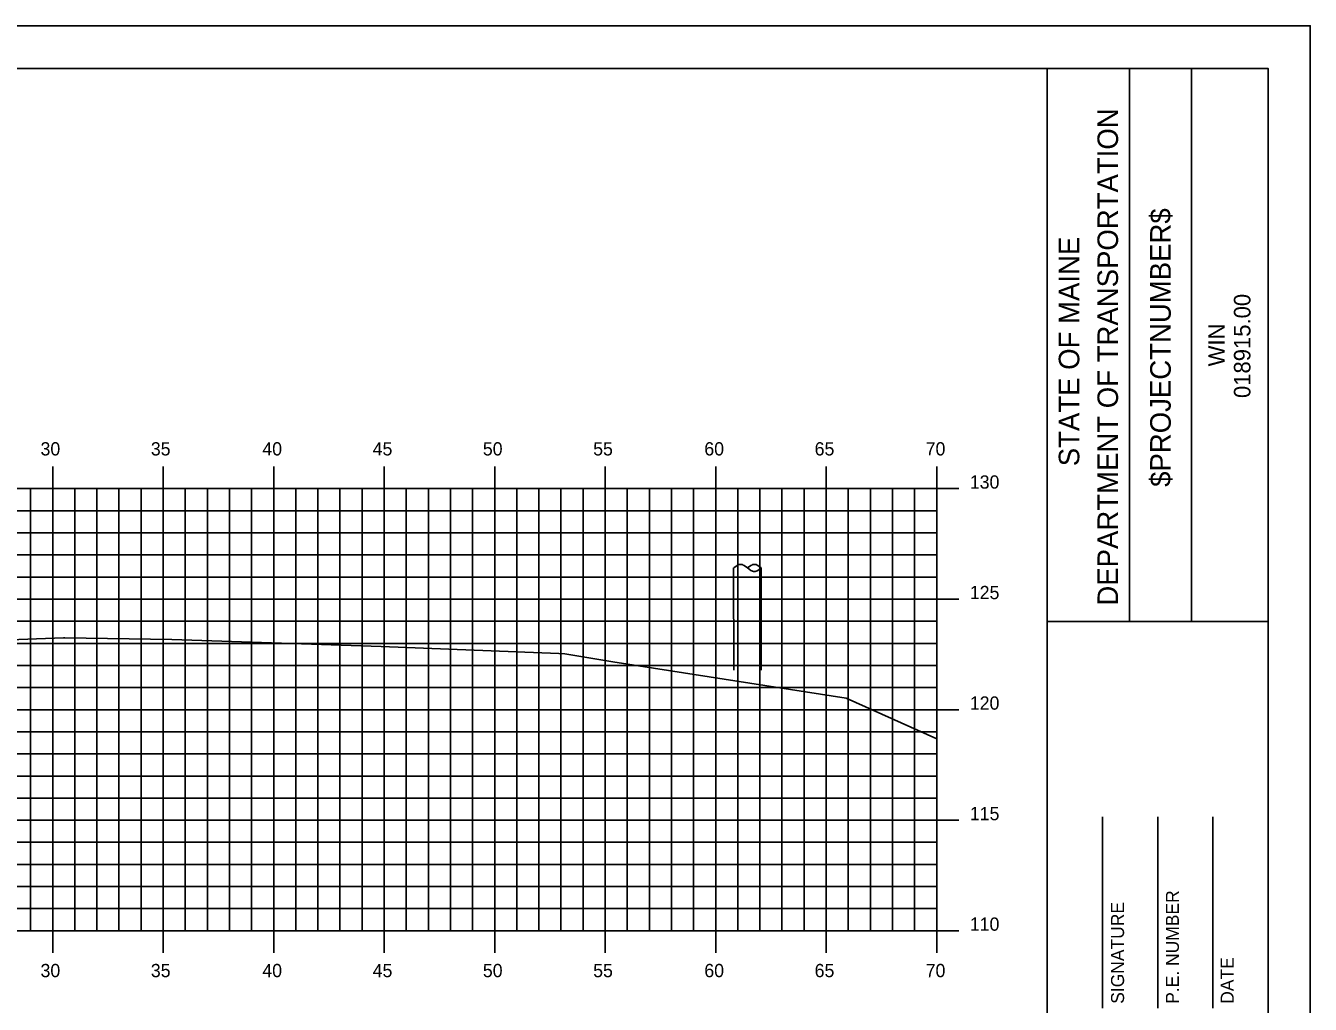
# Model space of a CAD drawing. Extents: x 852404 to 852575, y 365624 to 365734.
# Drawn here: x 852515.6 to 852573.7, y 365689.7 to 365734 of the extents above; entities that cross this region are included whole.
import ezdxf

# ---------------------------------------------------------------- set-up
doc = ezdxf.new("R2010")
doc.units = 0
for name, color, linetype in [('BORDER', 7, 'Continuous'), ('H_V ANNOTATION', 7, 'Continuous'), ('M_Roadway_Centerline', 7, 'Continuous'), ('MAJOR', 7, 'Continuous'), ('MINOR', 7, 'Continuous'), ('PLOT BOUNDARY', 7, 'Continuous'), ('S_Roadway_Centerline', 7, 'Continuous'), ('S_Utilities_Pole_StreetLight', 7, 'Continuous')]:
    doc.layers.add(name, color=color, linetype=linetype)

msp = doc.modelspace()

# ---------------------------------------------------------------- linework, layer by layer
at = {"layer": 'BORDER'}
for p, q in [((852561.792, 365627.027), (852561.792, 365732.027)), ((852565.521, 365707.024), (852565.521, 365732.024)), ((852568.316, 365707.024), (852568.316, 365732.024)), ((852561.793, 365707.021), (852571.792, 365707.021)), ((852564.292, 365689.53), (852564.292, 365698.177)), ((852566.792, 365689.53), (852566.792, 365698.177)), ((852569.292, 365689.53), (852569.292, 365698.177))]:
    msp.add_line(p, q, dxfattribs=at)
msp.add_lwpolyline([(852411.792, 365627.027), (852571.792, 365627.027), (852571.792, 365732.027), (852411.792, 365732.027)], close=True, dxfattribs=at)
at = {"layer": 'MAJOR'}
for p, q in [((852516.792, 365714.029), (852516.792, 365713.027)), ((852521.792, 365714.029), (852521.792, 365713.027)), ((852526.792, 365714.029), (852526.792, 365713.027)), ((852531.792, 365714.029), (852531.792, 365713.027)), ((852536.792, 365714.029), (852536.792, 365713.027)), ((852541.792, 365714.029), (852541.792, 365713.027)), ((852546.792, 365714.029), (852546.792, 365713.027)), ((852551.792, 365714.029), (852551.792, 365713.027)), ((852556.792, 365714.029), (852556.792, 365713.027)), ((852416.792, 365713.027), (852556.792, 365713.027)), ((852416.792, 365713.027), (852556.792, 365713.027)), ((852516.792, 365693.027), (852516.792, 365713.027)), ((852521.792, 365693.027), (852521.792, 365713.027)), ((852526.792, 365693.027), (852526.792, 365713.027)), ((852531.792, 365693.027), (852531.792, 365713.027)), ((852536.792, 365693.027), (852536.792, 365713.027)), ((852541.792, 365693.027), (852541.792, 365713.027)), ((852546.792, 365693.027), (852546.792, 365713.027)), ((852551.792, 365693.027), (852551.792, 365713.027)), ((852557.794, 365713.027), (852555.79, 365713.027)), ((852556.792, 365693.027), (852556.792, 365713.027)), ((852556.792, 365693.027), (852556.792, 365713.027)), ((852416.792, 365708.027), (852556.792, 365708.027)), ((852557.794, 365708.027), (852555.79, 365708.027)), ((852416.792, 365703.027), (852556.792, 365703.027)), ((852557.794, 365703.027), (852555.79, 365703.027)), ((852416.792, 365698.027), (852556.792, 365698.027)), ((852557.794, 365698.027), (852555.79, 365698.027)), ((852416.792, 365693.027), (852556.792, 365693.027)), ((852416.792, 365693.027), (852556.792, 365693.027)), ((852516.792, 365692.025), (852516.792, 365693.027)), ((852521.792, 365692.025), (852521.792, 365693.027)), ((852526.792, 365692.025), (852526.792, 365693.027)), ((852531.792, 365692.025), (852531.792, 365693.027)), ((852536.792, 365692.025), (852536.792, 365693.027)), ((852541.792, 365692.025), (852541.792, 365693.027)), ((852546.792, 365692.025), (852546.792, 365693.027)), ((852551.792, 365692.025), (852551.792, 365693.027)), ((852557.794, 365693.027), (852555.79, 365693.027)), ((852556.792, 365692.025), (852556.792, 365693.027))]:
    msp.add_line(p, q, dxfattribs=at)
at = {"layer": 'MINOR'}
for p, q in [((852515.792, 365693.027), (852515.792, 365713.027)), ((852517.792, 365693.027), (852517.792, 365713.027)), ((852518.792, 365693.027), (852518.792, 365713.027)), ((852519.792, 365693.027), (852519.792, 365713.027)), ((852520.792, 365693.027), (852520.792, 365713.027)), ((852522.792, 365693.027), (852522.792, 365713.027)), ((852523.792, 365693.027), (852523.792, 365713.027)), ((852524.792, 365693.027), (852524.792, 365713.027)), ((852525.792, 365693.027), (852525.792, 365713.027)), ((852527.792, 365693.027), (852527.792, 365713.027)), ((852528.792, 365693.027), (852528.792, 365713.027)), ((852529.792, 365693.027), (852529.792, 365713.027)), ((852530.792, 365693.027), (852530.792, 365713.027)), ((852532.792, 365693.027), (852532.792, 365713.027)), ((852533.792, 365693.027), (852533.792, 365713.027)), ((852534.792, 365693.027), (852534.792, 365713.027)), ((852535.792, 365693.027), (852535.792, 365713.027)), ((852537.792, 365693.027), (852537.792, 365713.027)), ((852538.792, 365693.027), (852538.792, 365713.027)), ((852539.792, 365693.027), (852539.792, 365713.027)), ((852540.792, 365693.027), (852540.792, 365713.027)), ((852542.792, 365693.027), (852542.792, 365713.027)), ((852543.792, 365693.027), (852543.792, 365713.027)), ((852544.792, 365693.027), (852544.792, 365713.027)), ((852545.792, 365693.027), (852545.792, 365713.027)), ((852547.792, 365693.027), (852547.792, 365713.027)), ((852548.792, 365693.027), (852548.792, 365713.027)), ((852549.792, 365693.027), (852549.792, 365713.027)), ((852550.792, 365693.027), (852550.792, 365713.027)), ((852552.792, 365693.027), (852552.792, 365713.027)), ((852553.792, 365693.027), (852553.792, 365713.027)), ((852554.792, 365693.027), (852554.792, 365713.027)), ((852555.792, 365693.027), (852555.792, 365713.027)), ((852416.792, 365712.027), (852556.792, 365712.027)), ((852556.792, 365712.027), (852555.79, 365712.027)), ((852416.792, 365711.027), (852556.792, 365711.027)), ((852556.792, 365711.027), (852555.79, 365711.027)), ((852416.792, 365710.027), (852556.792, 365710.027)), ((852556.792, 365710.027), (852555.79, 365710.027)), ((852416.792, 365709.027), (852556.792, 365709.027)), ((852556.792, 365709.027), (852555.79, 365709.027)), ((852416.792, 365707.027), (852556.792, 365707.027)), ((852556.792, 365707.027), (852555.79, 365707.027)), ((852416.792, 365706.027), (852556.792, 365706.027)), ((852556.792, 365706.027), (852555.79, 365706.027)), ((852416.792, 365705.027), (852556.792, 365705.027)), ((852556.792, 365705.027), (852555.79, 365705.027)), ((852416.792, 365704.027), (852556.792, 365704.027)), ((852556.792, 365704.027), (852555.79, 365704.027)), ((852416.792, 365702.027), (852556.792, 365702.027)), ((852556.792, 365702.027), (852555.79, 365702.027)), ((852416.792, 365701.027), (852556.792, 365701.027)), ((852556.792, 365701.027), (852555.79, 365701.027)), ((852416.792, 365700.027), (852556.792, 365700.027)), ((852556.792, 365700.027), (852555.79, 365700.027)), ((852416.792, 365699.027), (852556.792, 365699.027)), ((852556.792, 365699.027), (852555.79, 365699.027)), ((852416.792, 365697.027), (852556.792, 365697.027)), ((852556.792, 365697.027), (852555.79, 365697.027)), ((852416.792, 365696.027), (852556.792, 365696.027)), ((852556.792, 365696.027), (852555.79, 365696.027)), ((852416.792, 365695.027), (852556.792, 365695.027)), ((852556.792, 365695.027), (852555.79, 365695.027)), ((852416.792, 365694.027), (852556.792, 365694.027)), ((852556.792, 365694.027), (852555.79, 365694.027))]:
    msp.add_line(p, q, dxfattribs=at)
at = {"layer": 'PLOT BOUNDARY'}
msp.add_lwpolyline([(852403.699, 365623.968), (852573.699, 365623.968), (852573.699, 365733.968), (852403.699, 365733.968)], close=True, dxfattribs=at)
at = {"layer": 'S_Roadway_Centerline'}
msp.add_lwpolyline([(852514.448, 365706.178), (852517.274, 365706.274), (852517.34, 365706.273), (852522.187, 365706.197), (852531.654, 365705.889), (852539.699, 365705.561), (852539.969, 365705.546), (852542.133, 365705.196), (852552.698, 365703.551), (852556.792, 365701.707)], dxfattribs=at)
at = {"layer": 'S_Utilities_Pole_StreetLight'}
for p, q in [((852547.606, 365704.82), (852547.602, 365709.44)), ((852547.606, 365709.44), (852547.762, 365709.55)), ((852548.074, 365709.55), (852548.23, 365709.44)), ((852548.387, 365709.55), (852548.23, 365709.44)), ((852548.23, 365709.44), (852548.387, 365709.329)), ((852548.856, 365709.44), (852548.7, 365709.55)), ((852548.7, 365709.329), (852548.856, 365709.44)), ((852548.856, 365704.82), (852548.852, 365709.44))]:
    msp.add_line(p, q, dxfattribs=at)
for centre, start, end in [((852547.918, 365709.329), 90, 125.26439), ((852547.918, 365709.329), 54.73561, 90), ((852548.543, 365709.329), 90, 125.26439), ((852548.543, 365709.329), 54.73561, 90), ((852548.543, 365709.55), 234.73561, 270), ((852548.543, 365709.55), 270, 305.26439)]:
    msp.add_arc(centre, 0.271, start, end, dxfattribs=at)

# ---------------------------------------------------------------- texts
at = {"layer": 'BORDER'}
for s, height, p in [('DEPARTMENT OF TRANSPORTATION', 0.93176, (852564.999, 365707.733)), ('$PROJECTNUMBER$', 0.93176, (852567.384, 365713.106)), ('STATE OF MAINE', 0.93176, (852563.247, 365714.039)), ('018915.00', 0.7453, (852570.988, 365717.125)), ('WIN', 0.7453, (852569.829, 365718.557)), ('SIGNATURE', 0.5906, (852565.272, 365689.722)), ('P.E. NUMBER', 0.59055, (852567.753, 365689.722)), ('DATE', 0.5906, (852570.233, 365689.722))]:
    msp.add_text(s, height=height, rotation=90, dxfattribs=at).set_placement(p)
at = {"layer": 'H_V ANNOTATION'}
for s, p in [('30', (852516.241, 365714.527)), ('35', (852521.233, 365714.527)), ('40', (852526.278, 365714.527)), ('45', (852531.27, 365714.527)), ('50', (852536.256, 365714.527)), ('55', (852541.248, 365714.527)), ('60', (852546.278, 365714.527)), ('65', (852551.27, 365714.527)), ('70', (852556.294, 365714.527)), ('130', (852558.292, 365713.027)), ('125', (852558.292, 365708.027)), ('120', (852558.292, 365703.027)), ('115', (852558.292, 365698.027)), ('110', (852558.292, 365693.027)), ('30', (852516.241, 365690.927)), ('35', (852521.233, 365690.927)), ('40', (852526.278, 365690.927)), ('45', (852531.27, 365690.927)), ('50', (852536.256, 365690.927)), ('55', (852541.248, 365690.927)), ('60', (852546.278, 365690.927)), ('65', (852551.27, 365690.927)), ('70', (852556.294, 365690.927))]:
    msp.add_text(s, height=0.6, dxfattribs=at).set_placement(p)
at = {"layer": 'M_Roadway_Centerline'}
for s, p in [('C', (852517.269, 365706.274)), ('L', (852517.274, 365706.266))]:
    msp.add_text(s, height=0.0146, dxfattribs=at).set_placement(p)

doc.saveas('drawing.dxf')
